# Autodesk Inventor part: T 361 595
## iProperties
Company: Mayer & Müller AG Schaltgeräte
Created: 2006-07
Part Number: T 361 595
Material: Umabord KE
Document SubType Name: Modeling
Designer: I.Baliuc
Manufacturer: Standard
Standards Organization: Custom
Description: Isolierplatte
Density: 0.94 g/cm^3
Zweck: für Blendengrundplatte
Abmessung: 112 x 3 - 262
Author: T.Messerschmitt
Revision Number: 361595
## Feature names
1. Extrusion2
2. Bohrung_Ø18 [Hole]
3. Bohrung_Ø6.5_01 [Hole]
4. Bohrung_Ø6.5_02 [Hole]
